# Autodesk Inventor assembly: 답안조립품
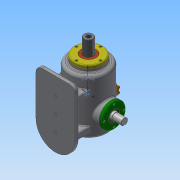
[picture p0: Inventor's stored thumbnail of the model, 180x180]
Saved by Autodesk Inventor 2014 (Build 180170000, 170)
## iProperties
Created: 2018-04
Part Number: 답안조립품
Document SubType Name: Assembly
Designer: net
Mass: 5764.01 g
Surface Area: 4274.04 cm^2
Volume: 2081.36 cm^3
Density: 2.76935 g/cm^3
Author: net
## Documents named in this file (17)
- C:\Users\net\Desktop\380407V1023\답안조립품.iam
- C:\Users\net\Desktop\380407V1023\본체.ipt
- C:\Users\net\Desktop\380407V1023\축 커버-1.ipt
- C:\Users\net\Desktop\380407V1023\축 커버-2.ipt
- C:\Users\net\Desktop\380407V1023\슬라이드 커버.ipt
- C:\Users\net\Desktop\380407V1023\베어링 6205.ipt
- 베어링 6205.ipt
- C:\Users\net\Desktop\380407V1023\편심축.ipt
- C:\Users\net\Desktop\380407V1023\오일실.ipt
- 오일실.ipt
- C:\Users\net\Desktop\380407V1023\슬라이드.ipt
- C:\Users\net\Desktop\380407V1023\부시.ipt
- C:\Users\net\Desktop\380407V1023\볼트 M4.ipt
- 볼트 M4.ipt
- C:\Users\net\Desktop\380407V1023\상부 캡.ipt
- C:\Users\net\Desktop\380407V1023\플레이트.ipt
- C:\Users\net\Desktop\380407V1023\가변스프링.ipt
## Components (2 placed, 2 different names)
1. 플레이트:1
2. 가변스프링:1
